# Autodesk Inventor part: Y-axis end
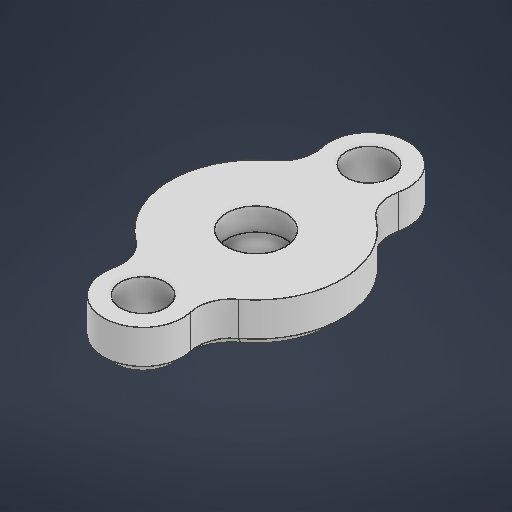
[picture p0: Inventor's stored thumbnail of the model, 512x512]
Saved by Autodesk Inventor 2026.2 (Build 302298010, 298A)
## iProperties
Created: 2026-04
Part Number: Y-axis end
Material: 일반
Document SubType Name: Modeling
Designer: work
Density: 1 g/cm^3
Appearance: 기본값
Author: work
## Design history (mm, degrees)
sketch "스케치1"
  geometry: L1 (0, 10)-(0, -10); C1 r 7.6 at (0, 0); C2 r 2 at (0, 10); C3 r 2 at (0, -10); C4 r 3.5 at (0, 10); C5 r 3.5 at (0, -10); 5 further points
  constraints: 5 centre point, 5 coincident, 2 end point, 1 midpoint, 1 vertical
  dimensions: "d0" = 20 distance of L1.start L1.end; "d1" = 4 diameter of C2; "d2" = 4 diameter of C3; "d3" = 7 diameter of C4; "d4" = 7 diameter of C5; "d5" = 15.2 diameter of C1
extrude "돌출1" new body sketch "스케치1" distance "d6" = 4; taper "d7" = 0 deg
sketch "스케치2"
  geometry: C1 r 2.6 at (0, 0); 1 further point
  constraints: 1 centre point, 1 coincident
  dimensions: "d8" = 5.2 diameter of C1
extrude "돌출2" cut sketch "스케치2" distance "d9" = 2; taper "d10" = 0 deg
fillet "모깎기1" dims "d11" = 3
chamfer "모따기1" distance "d12" = 1; stored, may be unused: second distance "d13" = 2, angle "d14" = 45 deg
node "솔리드1"
